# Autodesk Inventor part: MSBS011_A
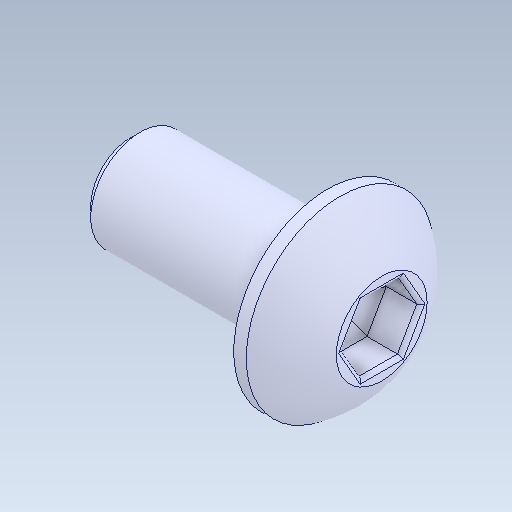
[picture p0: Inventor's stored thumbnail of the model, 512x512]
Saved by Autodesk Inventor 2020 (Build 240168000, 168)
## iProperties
Created: 2017-09
Part Number: MSBS011_A
Material: Générique
Document SubType Name: Modeling
Designer: bruno
Density: 1 g/cm^3
Appearance: Par défaut
Author: bruno
Sending System: SolidWorks 2016
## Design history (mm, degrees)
feature "Importée1"
node "Solide1"
